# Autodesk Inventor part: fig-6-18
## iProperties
Created: 2004-05
Part Number: fig-6-18
Document SubType Name: Modeling
Designer: CADCIM Technologies
Manufacturer: Standard
Standards Organization: Custom
Density: 1 g/cm^3
Author: CADCIM Technologies
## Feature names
1. Extrusion1
2. Extrusion2
3. Extrusion3
4. Extrusion4
5. Extrusion5
6. Extrusion6
7. Extrusion7
